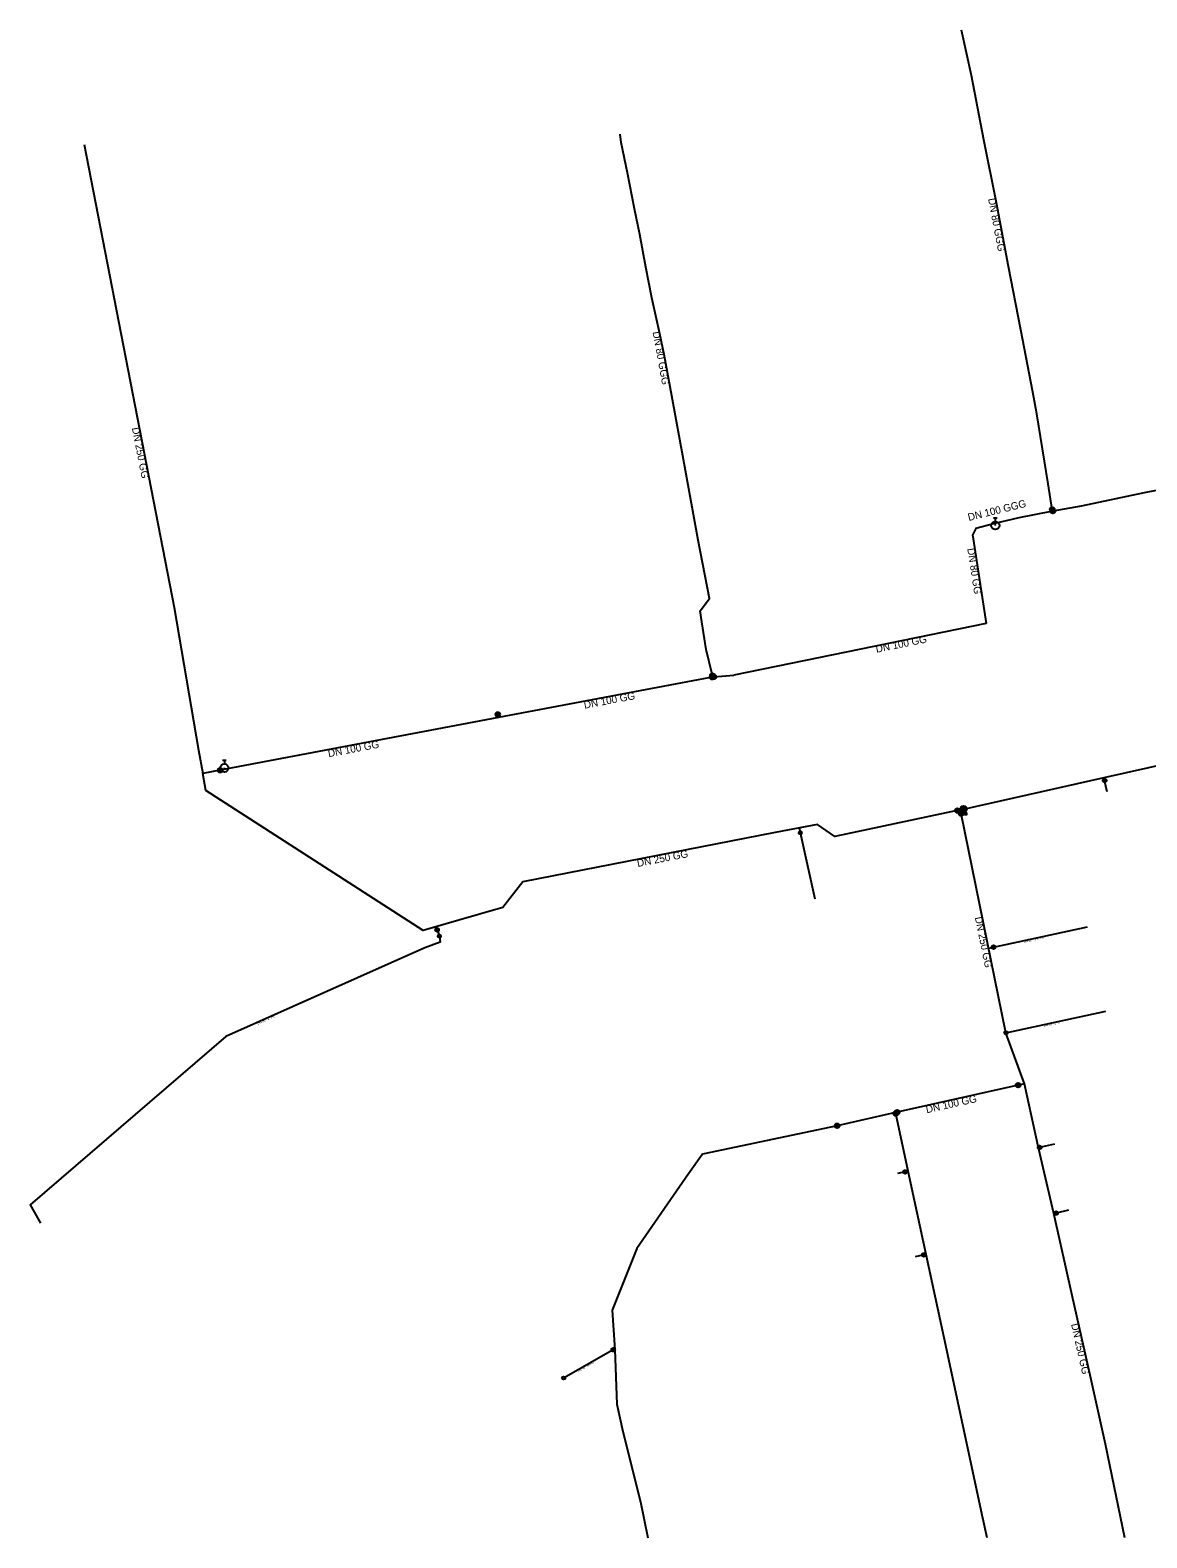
# Model space of a CAD drawing. Extents: x -452548 to -451108, y -1100145 to -1099658.
# Drawn here: x -452548.4 to -452307.3, y -1100145 to -1099819.8 of the extents above; entities that cross this region are included whole.
import ezdxf

# ---------------------------------------------------------------- set-up
doc = ezdxf.new("R2010")
doc.units = 0
for name, color, linetype in [('_hydrantova_odbocka_', 7, 'Continuous'), ('_pripojka_prevzato_z_dokumentace_', 7, 'Continuous'), ('_pripojka_priblizne_', 7, 'Continuous'), ('_voda_smvak_prevzato_z_dokumentace_', 7, 'Continuous'), ('Default', 7, 'Continuous'), ('MoLevel 27', 7, 'Continuous'), ('MoLevel 28', 7, 'Continuous'), ('MoLevel 30', 7, 'Continuous'), ('MoLevel 32', 7, 'Continuous'), ('MoLevel 42', 7, 'Continuous'), ('MoLevel 46', 7, 'Continuous'), ('MoLevel 53', 7, 'Continuous'), ('MoLevel 55', 7, 'Continuous')]:
    doc.layers.add(name, color=color, linetype=linetype)

# ---------------------------------------------------------------- blocks, each defined once
blk = doc.blocks.new('_uzaver_')
at = {"layer": 'Default'}
for p, q in [((-0.000035, -0.000035), (0.000035, 0.000035)), ((0.000035, -0.000035), (-0.000035, 0.000035))]:
    blk.add_line(p, q, dxfattribs=at)
for radius in [0.00005, 0.0000025]:
    blk.add_circle((0, 0), radius, dxfattribs=at)
blk = doc.blocks.new('_uzaver_pripojka_')
at = {"layer": 'Default'}
for p, q in [((-0.000035, -0.000035), (0.000035, 0.000035)), ((0.000035, -0.000035), (-0.000035, 0.000035))]:
    blk.add_line(p, q, dxfattribs=at)
for radius in [0.00005, 0.0000025]:
    blk.add_circle((0, 0), radius, dxfattribs=at)
blk = doc.blocks.new('_hydrant_voda_')
at = {"layer": 'Default'}
for p, q in [((-0.000023, 0.000095), (0.000023, 0.000095)), ((0, 0.000095), (0, 0.00005))]:
    blk.add_line(p, q, dxfattribs=at)
blk.add_circle((0, 0), 0.00005, dxfattribs=at)
blk = doc.blocks.new('_sachta_voda_')
at = {"layer": 'Default'}
blk.add_circle((0, 0), 0.000035, dxfattribs=at)
blk = doc.blocks.new('_poklop_voda_')
at = {"layer": 'Default'}
blk.add_lwpolyline([(-0.00002, 0.00002), (0.00002, 0.00002), (0.00002, -0.00002), (-0.00002, -0.00002), (-0.00002, 0.00002)], dxfattribs=at)

msp = doc.modelspace()

# ---------------------------------------------------------------- linework, layer by layer
at = {"layer": '_hydrantova_odbocka_'}
for p, q in [((-452340.16, -1099926.25), (-452340.06, -1099926.63)), ((-452506.5, -1099979.27), (-452506.49, -1099978.96))]:
    msp.add_line(p, q, dxfattribs=at)
at = {"layer": '_pripojka_prevzato_z_dokumentace_'}
msp.add_line((-452337.76, -1100036.09), (-452316.22, -1100031.44), dxfattribs=at)
for points in [[(-452315.92, -1099984.07), (-452316.45, -1099981.63), (-452316.58, -1099981.03)], [(-452341.49, -1100017.85), (-452340.42, -1100017.62), (-452320.15, -1100013.25)], [(-452327.27, -1100060.14), (-452330.48, -1100060.83), (-452330.76, -1100060.88)], [(-452358.85, -1100065.95), (-452359.49, -1100066.1), (-452361.18, -1100066.46)], [(-452324.23, -1100074.39), (-452326.94, -1100074.98), (-452327.44, -1100075.08)], [(-452354.98, -1100083.9), (-452355.48, -1100084.01), (-452357.35, -1100084.41)], [(-452422.2, -1100104.48), (-452422.54, -1100104.48), (-452433.27, -1100110.57)]]:
    msp.add_lwpolyline(points, dxfattribs=at)
at = {"layer": '_pripojka_priblizne_'}
for p, q in [((-452382.14, -1099992.95), (-452382.34, -1099991.89)), ((-452378.96, -1100007.25), (-452382.14, -1099992.95))]:
    msp.add_line(p, q, dxfattribs=at)
for points in [[(-452460.81, -1100013.22), (-452460.57, -1100013.88), (-452460.08, -1100015.23)], [(-452460.08, -1100015.23), (-452459.89, -1100016.57), (-452463.23, -1100017.75), (-452506.21, -1100036.92), (-452548.44, -1100073.19), (-452546.23, -1100077.13)]]:
    msp.add_lwpolyline(points, dxfattribs=at)
at = {"layer": '_voda_smvak_prevzato_z_dokumentace_'}
for p, q in [((-452327.77, -1099923.59), (-452327.77, -1099923.16)), ((-452344.89, -1099929.05), (-452344.82, -1099929.49)), ((-452344.82, -1099929.49), (-452342, -1099947.76)), ((-452342, -1099947.76), (-452396.51, -1099958.95)), ((-452401.53, -1099959.42), (-452447.35, -1099968.07)), ((-452401.53, -1099959.42), (-452401.22, -1099959.38)), ((-452401.22, -1099959.38), (-452401.02, -1099959.35)), ((-452401.02, -1099959.35), (-452401.14, -1099959.02)), ((-452401.02, -1099959.35), (-452400.82, -1099959.32)), ((-452400.82, -1099959.32), (-452396.51, -1099958.95)), ((-452447.35, -1099968.07), (-452507.4, -1099979.44)), ((-452447.46, -1099967.4), (-452447.35, -1099968.07)), ((-452507.4, -1099979.44), (-452511.18, -1099980.16)), ((-452348.26, -1099988.15), (-452367.6, -1099992.26)), ((-452347.59, -1099988.01), (-452348.26, -1099988.15)), ((-452347.59, -1099988.01), (-452346.93, -1099987.86)), ((-452347.43, -1099988.79), (-452347.59, -1099988.01)), ((-452335.13, -1100047.39), (-452361.24, -1100053.23)), ((-452333.73, -1100047.07), (-452335.13, -1100047.39)), ((-452361.24, -1100053.23), (-452361.58, -1100053.31)), ((-452361.58, -1100053.31), (-452374.19, -1100056.14)), ((-452361.53, -1100053.52), (-452361.58, -1100053.31))]:
    msp.add_line(p, q, dxfattribs=at)
for points in [[(-452327.77, -1099923.16), (-452328.63, -1099917.65), (-452331.09, -1099902.52), (-452331.96, -1099897.91), (-452334.58, -1099884.46), (-452337.21, -1099870.79), (-452339.82, -1099857.05), (-452342.51, -1099843.47), (-452345.21, -1099829.53), (-452347.34, -1099819.78)], [(-452536.75, -1099844.42), (-452517.31, -1099944.34), (-452512.08, -1099975.13), (-452511.18, -1099980.16)], [(-452401.14, -1099959.02), (-452402.49, -1099953.4), (-452403.44, -1099947.41), (-452403.77, -1099945.03), (-452401.74, -1099942.39), (-452404.19, -1099929.83), (-452407.38, -1099912.44), (-452409.91, -1099898.64), (-452411.54, -1099889.78), (-452412.52, -1099885.29), (-452414.23, -1099877.5), (-452415.48, -1099870.93), (-452416.82, -1099863.9), (-452417.93, -1099858.32), (-452419.47, -1099850.59), (-452420.8, -1099843.99), (-452421.06, -1099842.25)], [(-452280.76, -1099914.36), (-452307.91, -1099919.59), (-452321.54, -1099922.48), (-452327.65, -1099923.56)], [(-452346.93, -1099987.86), (-452316.58, -1099981.03), (-452302.11, -1099977.8), (-452284.59, -1099973.89), (-452266.73, -1099969.9), (-452234.9, -1099962.8), (-452147.49, -1099943.29), (-452132.25, -1099940.24), (-452115.2, -1099936.84), (-452096.89, -1099933.18), (-452079.42, -1099929.69), (-452064.98, -1099926.81), (-452051.17, -1099924.05), (-452046.02, -1099949.05), (-452030.12, -1099945.84), (-452027.65, -1099944.96)], [(-452327.98, -1099923.63), (-452335, -1099924.98), (-452340.16, -1099926.25), (-452344.24, -1099927.26), (-452344.97, -1099928.71), (-452344.89, -1099929.05)], [(-452327.65, -1099923.56), (-452327.77, -1099923.59), (-452327.98, -1099923.63)], [(-452455.89, -1100011.8), (-452463.57, -1100014.03), (-452510.53, -1099983.82), (-452511.18, -1099980.16)], [(-452367.6, -1099992.26), (-452374.67, -1099993.76), (-452378.45, -1099991.13), (-452387.58, -1099992.91), (-452442.08, -1100003.52), (-452446.4, -1100009.05), (-452455.89, -1100011.8)], [(-452333.73, -1100047.07), (-452337.76, -1100036.09), (-452347.43, -1099988.79)], [(-452312.11, -1100145.05), (-452316.25, -1100124.84), (-452319.45, -1100110.59), (-452323.45, -1100092.79), (-452327.44, -1100075.08), (-452330.76, -1100060.88), (-452333.73, -1100047.07)], [(-452374.19, -1100056.14), (-452403.25, -1100062.25), (-452406.32, -1100066.5), (-452417.42, -1100082.65), (-452422.76, -1100095.95), (-452422.2, -1100104.48), (-452421.77, -1100116.18), (-452420.45, -1100122.13), (-452416.67, -1100137.28), (-452415.07, -1100145.05)], [(-452341.82, -1100145.05), (-452342.73, -1100140.81), (-452351.1, -1100101.9), (-452354.98, -1100083.9), (-452358.85, -1100065.95), (-452361.53, -1100053.52)]]:
    msp.add_lwpolyline(points, dxfattribs=at)

# ---------------------------------------------------------------- block references
at = {"layer": 'MoLevel 27'}
for p, xscale, yscale, rotation in [((-452327.77, -1099923.16), 10000, 9999.999999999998, 98.8798335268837), ((-452327.65, -1099923.56), 9999.999999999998, 10000.000000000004, 10.041126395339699), ((-452401.22, -1099959.38), 10000, 10000, 5.367606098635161), ((-452401.14, -1099959.02), 10000.000000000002, 9999.999999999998, 99.0989654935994), ((-452400.82, -1099959.32), 10000, 10000, 4.882494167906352), ((-452447.46, -1099967.4), 10000, 10000.000000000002, 99.4601960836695), ((-452507.4, -1099979.44), 10000, 9999.999999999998, 10.719183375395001), ((-452348.26, -1099988.15), 10000, 9999.999999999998, 11.994597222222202), ((-452346.93, -1099987.86), 10000, 9999.999999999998, 12.682669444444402), ((-452347.43, -1099988.79), 10000.000000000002, 9999.999999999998, -78.43820555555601), ((-452335.13, -1100047.39), 10000, 10000, 12.621097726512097), ((-452361.24, -1100053.23), 10000, 10000, 12.6253582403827)]:
    msp.add_blockref('_uzaver_', p, dxfattribs=dict(at, xscale=xscale, yscale=yscale, rotation=rotation))
at = {"layer": 'MoLevel 27', "xscale": 10000, "yscale": 10000}
for p in [(-452361.53, -1100053.52), (-452374.19, -1100056.14)]:
    msp.add_blockref('_uzaver_', p, dxfattribs=at)
at = {"layer": 'MoLevel 28', "xscale": 17636.68430335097, "yscale": 17636.68430335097}
for p in [(-452340.06, -1099926.64), (-452506.49, -1099978.96)]:
    msp.add_blockref('_hydrant_voda_', p, dxfattribs=at)
at = {"layer": 'MoLevel 30'}
for p, xscale, yscale in [((-452346.93, -1099987.86), 20000, 20000), ((-452382.14, -1099992.95), 10000, 10000), ((-452460.08, -1100015.23), 10000, 10000), ((-452337.76, -1100036.09), 10000, 10000), ((-452433.27, -1100110.57), 10000, 10000)]:
    msp.add_blockref('_sachta_voda_', p, dxfattribs=dict(at, xscale=xscale, yscale=yscale))
at = {"layer": 'MoLevel 42', "xscale": 10000, "yscale": 10000}
msp.add_blockref('_poklop_voda_', (-452346.46, -1099988.86), dxfattribs=at)
at = {"layer": 'MoLevel 53', "xscale": 7999.999999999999, "yscale": 7999.999999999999}
for p in [(-452316.45, -1099981.64), (-452460.57, -1100013.88), (-452340.42, -1100017.62), (-452330.48, -1100060.83), (-452359.51, -1100066.1), (-452326.94, -1100074.98), (-452355.48, -1100084.01), (-452422.54, -1100104.48)]:
    msp.add_blockref('_uzaver_pripojka_', p, dxfattribs=at)

# ---------------------------------------------------------------- texts
at = {"layer": 'MoLevel 32'}
msp.add_text("DN 25 - 1'' PE", height=0.455, rotation=24.0297, dxfattribs=at).set_placement((-452499.24, -1100034.31))
at = {"layer": 'MoLevel 46'}
for s, rotation, p in [('DN 80 GGG', 280.773, (-452341.62, -1099856.17)), ('DN 80 GGG', 280.3902, (-452414.06, -1099884.92)), ('DN 250 GG', 281.009, (-452526.47, -1099905.62)), ('DN 100 GGG', 13.8715, (-452345.77, -1099925.68)), ('DN 80 GG', 278.7648, (-452346.11, -1099931.65)), ('DN 100 GG', 11.6003, (-452365.7, -1099954.11)), ('DN 100 GG', 10.6933, (-452428.73, -1099966.18)), ('DN 100 GG', 10.7184, (-452483.98, -1099976.64)), ('DN 250 GG', 11.0185, (-452417.25, -1100000.32)), ('DN 250 GG', 281.5618, (-452344.48, -1100011.21)), ('DN 100 GG', 12.6254, (-452354.86, -1100053.45)), ('DN 250 GG', 282.6769, (-452323.71, -1100098.97))]:
    msp.add_text(s, height=1.605, rotation=rotation, dxfattribs=at).set_placement(p)
at = {"layer": 'MoLevel 55'}
for s, rotation, p in [("DN 32 - 5/4'' PE", 12.1812, (-452333.86, -1100016.67)), ("DN 50 - 2'' O", 12.1705, (-452329.56, -1100034.79)), ('DN 40 - 6/4 O', 29.5698, (-452430.11, -1100109.3))]:
    msp.add_text(s, height=0.455, rotation=rotation, dxfattribs=at).set_placement(p)

doc.saveas('drawing.dxf')
